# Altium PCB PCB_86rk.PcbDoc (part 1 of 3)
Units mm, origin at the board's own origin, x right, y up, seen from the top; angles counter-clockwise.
Board outline 185 x 150 mm, 2 copper layers (Top Layer, Bottom Layer); 95 components, 233 nets, 810 pads, 336 vias.
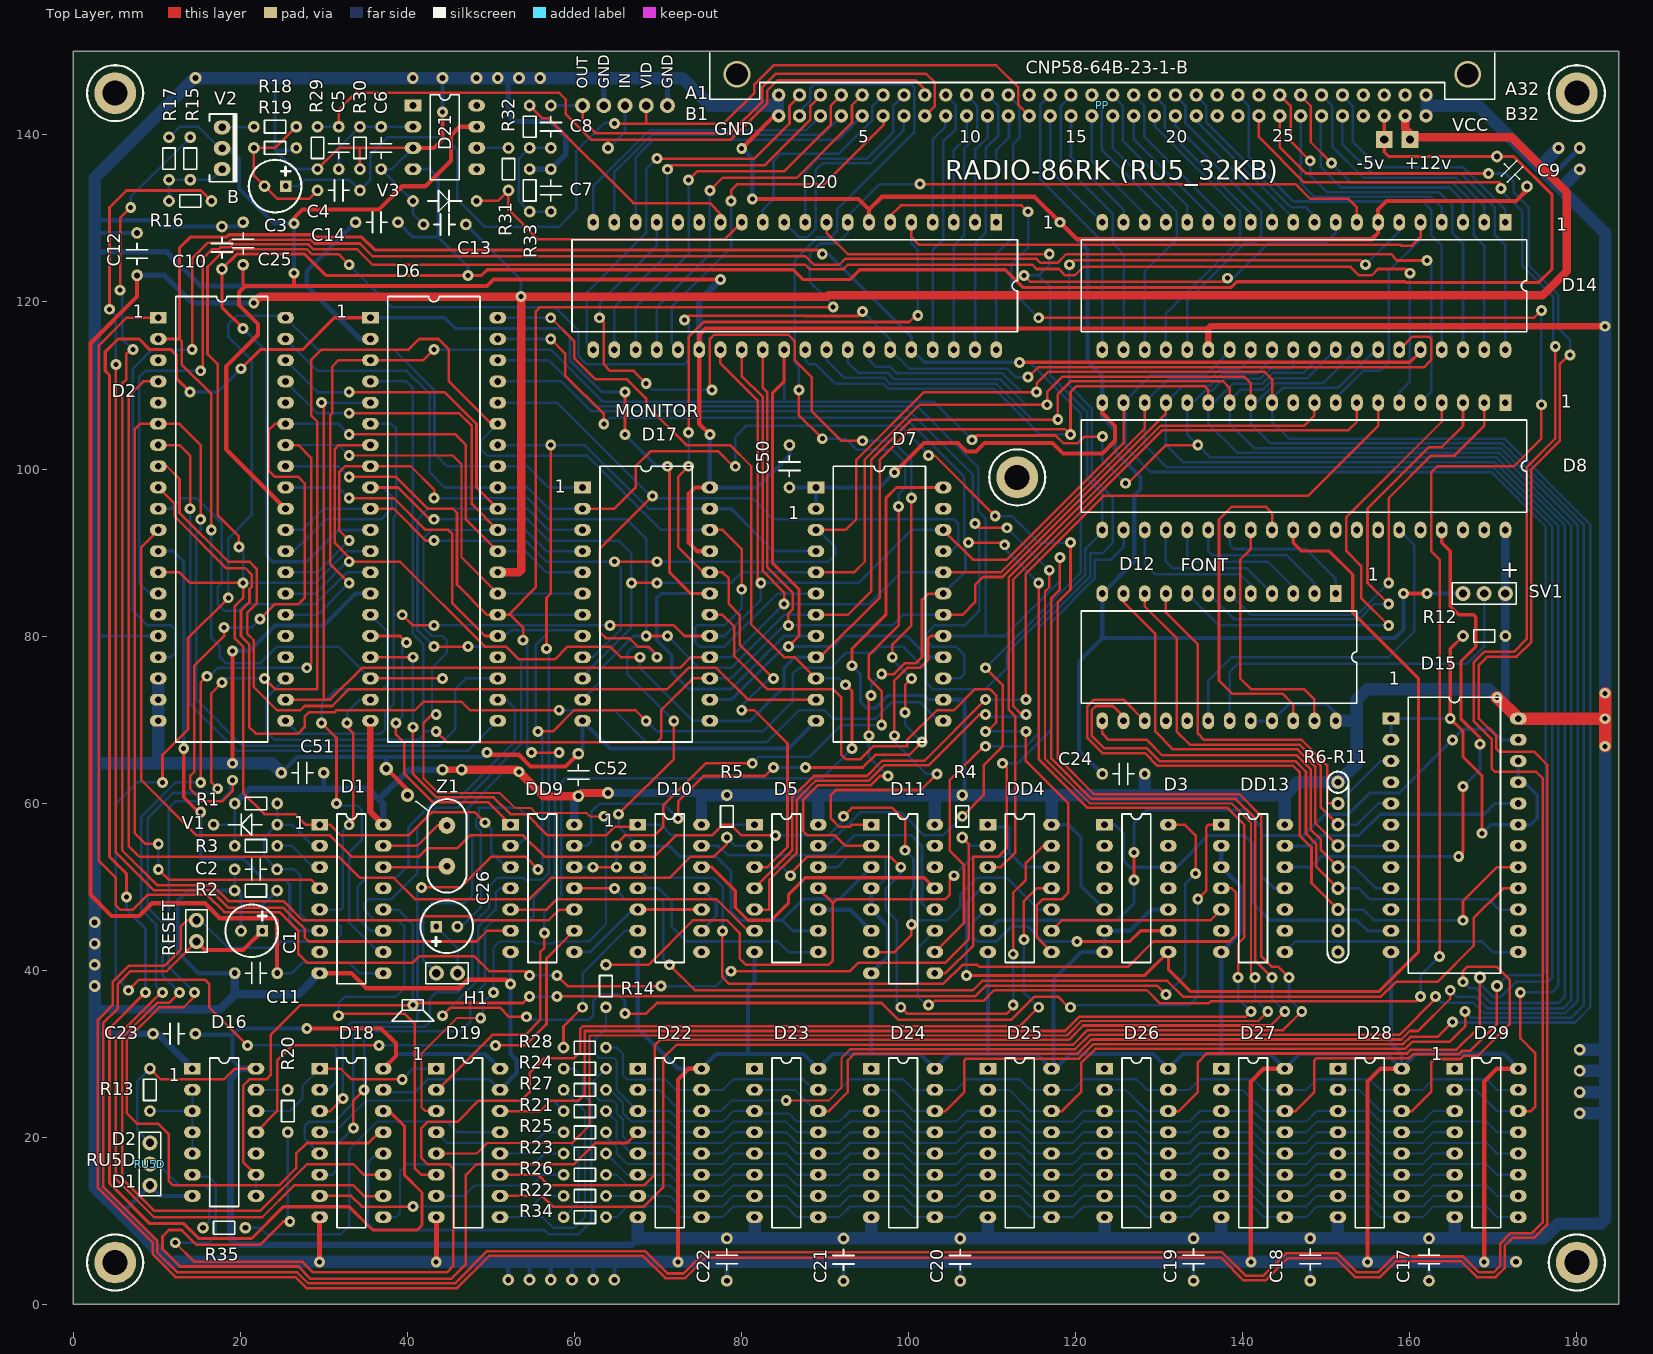
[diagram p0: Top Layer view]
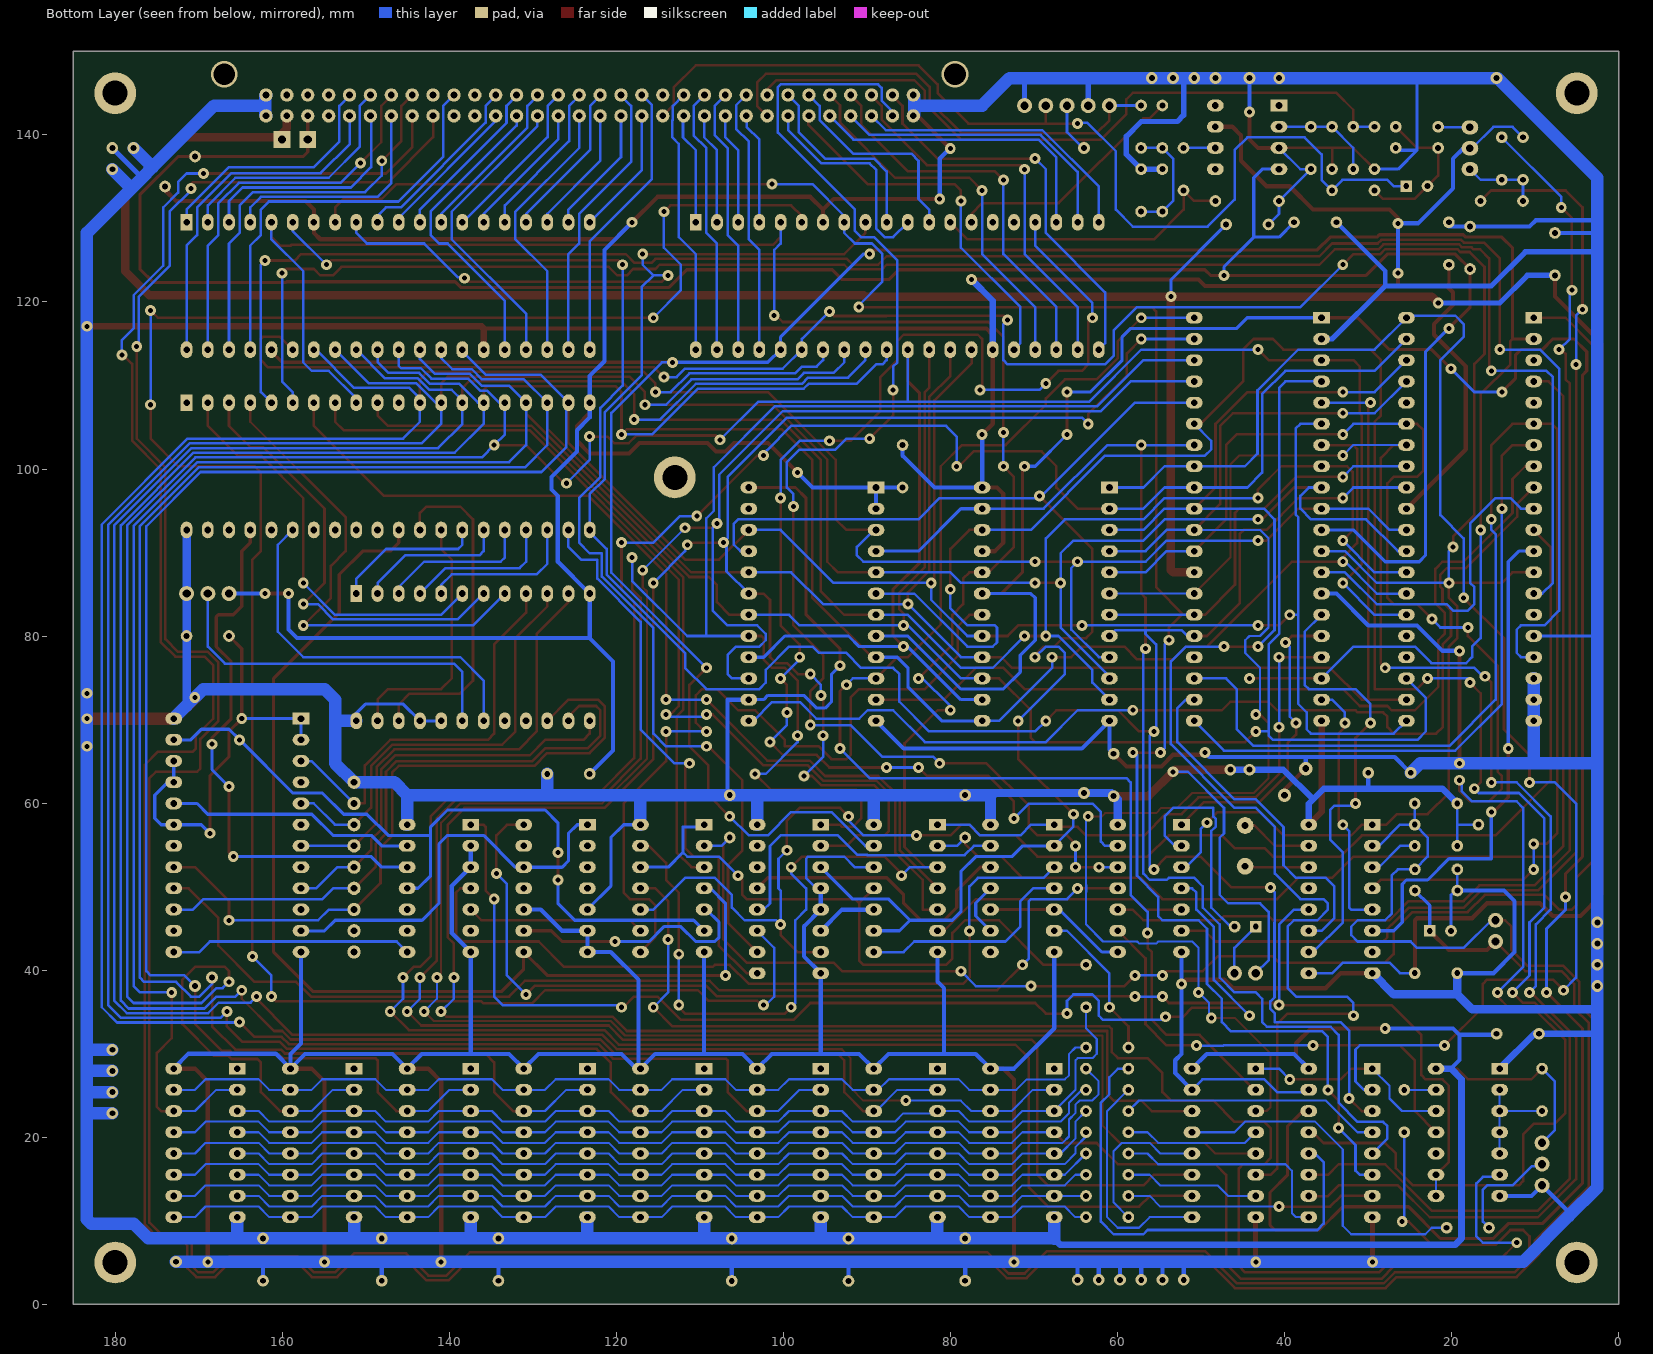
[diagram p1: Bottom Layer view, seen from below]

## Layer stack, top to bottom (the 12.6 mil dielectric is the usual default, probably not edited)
Top Layer: signal copper 0.0356
Dielectric: dielectric 0.32, FR-4, Dk 4.8
Bottom Layer: signal copper 0.0356

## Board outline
0,0 185,0 185,150 0,150

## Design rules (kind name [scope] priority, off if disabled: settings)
Clearance [All] p1: gap=0.254
ComponentClearance [All] p1: gap=0 collisioncheckmode=3 verticalgap=0 showdistances=FALSE
PolygonConnect [All] p1: connectstyle=Relief reliefconductorwidth=0.254 reliefentries=4 polygonreliefangle="90 Angle"
RoutingVias [All] p1: holewidth=0.6 width=1.3 viastyle="Through Hole" minholewidth=0.6 minwidth=1.3 maxholewidth=0.6 maxwidth=1.3
SilkscreenOverComponentPads [All] p1: minsilkscreentomaskgap=0.254
SolderMaskExpansion [All] p1: expansion=0.102
Width [All] p1: maxlimit=3 minlimit=0.254 preferedwidth=0.254
26 further rules are at their usual default settings.

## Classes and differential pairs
net class C[1..47]: C1 C2 C3 C4 C5 C6 C7 C8 C9 C10 C11 C12 C13 C14 C15 C16 C17 C18 C19 C20 C21 C22 C23 C24 C25 C26 C27 C28 C29 C30 C31 C32 C33 C34 C35 C36 C37 C38 C39 C40 C41 C42 C43 C44 C45 C46 C47
net class B[1..11]: B1 B2 B3 B4 B5 B6 B7 B8 B9 B10 B11

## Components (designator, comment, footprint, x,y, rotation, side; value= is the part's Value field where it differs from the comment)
C1 "C" Cap_2.54-6.3mm 21.336,44.704 r180 top
C2 "CAP" Cap_5mm 19.304,52.07 r0 top
C3 "C" Cap_2.54-6.3mm 24.146,133.874 r180 top
C4 "CAP" Cap_5mm 34.306,133.366 r180 top
C5 "CAP" Cap_5mm 31.766,135.906 r90 top
C6 "CAP" Cap_5mm 36.846,140.986 r270 top
C7 "CAP" Cap_5mm 57.166,130.826 r90 top
C8 "CAP" Cap_5mm 57.166,138.446 r90 top
C9 "CAP" Cap_5mm 170.434,137.414 r315 top
C10 "CAP" Cap_5mm 17.78,123.952 r90 top
C11 "CAP" Cap_5mm 24.4,39.64 r180 top
C12 "CAP" Cap_5mm 7.62,123.19 r90 top
C13 "CAP" Cap_5mm 46.99,129.286 r180 top
C14 "CAP" Cap_5mm 38.862,129.54 r180 top
C17 "CAP" Cap_5mm 162.306,7.89 r270 top
C18 "CAP" Cap_5mm 148.082,7.89 r270 top
C19 "CAP" Cap_5mm 134.112,7.89 r270 top
C20 "CAP" Cap_5mm 106.172,7.874 r270 top
C21 "CAP" Cap_5mm 92.202,7.874 r270 top
C22 "CAP" Cap_5mm 78.232,7.89 r270 top
C23 "CAP" Cap_5mm 14.605,32.385 r180 top
C24 "CAP" Cap_5mm 128.27,63.5 r180 top
C25 "CAP" Cap_5mm 20.32,124.46 r90 top
C26 "C" Cap_2.54-6.3mm 44.704,45.212 r0 top
C50 "CAP" Cap_5mm 85.725,102.87 r270 top
C51 "CAP" Cap_5mm 29.972,63.627 r180 top
C52 "CAP" Cap_5mm 60.452,65.913 r270 top
D1 "КР580ГФ24" DIP16 29.48,57.42 r0 top
D2 "КР580ИК57" DIP40_2.54 10.16,118.11 r0 top
D3 "К155ИЕ4" DIP14 123.46,57.42 r0 top
D5 "К555ЛП5" DIP14 81.55,57.42 r0 top
D6 "КР580ВМ80А" DIP40_2.54 35.56,118.11 r0 top
D7 "К589ИР12" DIP24 88.9,97.79 r0 top
D8 "КР580ВГ75" DIP40_2.54 171.45,107.95 r270 top
D10 "К555ЛА3" DIP14 67.58,57.42 r0 top
D11 "К555ИД7" DIP16 95.52,57.42 r0 top
D12 "2764" DIP24 151.13,85.09 r270 top
D14 "КР580ВВ55" DIP40_2.54 171.45,129.54 r270 top
D15 "К155ИР13" DIP24 157.75,70.12 r0 top
D16 "К155ИР1" DIP14 14.24,28.21 r0 top
D17 "2764" DIP24 60.96,97.79 r0 top
D18 "КР555КП11" DIP16 29.48,28.21 r0 top
D19 "КР555КП11" DIP16 43.45,28.21 r0 top
D20 "КР580ВВ55" DIP40_2.54 110.49,129.54 r270 top
D21 "КР140УД608" DIP8 40.656,143.526 r0 top
D22 "КР565РУ5" DIP16 67.58,28.21 r0 top
D23 "КР565РУ5" DIP16 81.55,28.21 r0 top
D24 "КР565РУ5" DIP16 95.52,28.21 r0 top
D25 "КР565РУ5" DIP16 109.49,28.21 r0 top
D26 "КР565РУ5" DIP16 123.46,28.21 r0 top
D27 "КР565РУ5" DIP16 137.43,28.21 r0 top
D28 "КР565РУ5" DIP16 151.4,28.21 r0 top
D29 "КР565РУ5" DIP16 165.37,28.21 r0 top
DD4 "К555ЛИ1" DIP14 109.49,57.42 r0 top
DD9 "К555ЛН1" DIP14 52.34,57.42 r0 top
DD13 "К555ТМ2" DIP14 137.43,57.42 r0 top
H1 "PLS-2" PLS-2 45.99,39.64 r180 top
PP "СНП58-64В-23-1-В" SNP58-64B-23-1(2) 123.19,144.78 r0 top
R1 "RES" RES_5 24.4,59.96 r180 top
R2 "RES" RES_5 19.304,49.53 r0 top
R3 "RES" RES_5 19.32,54.88 r0 top
R4 "RES" RES_5 106.426,55.88 r90 top
R5 "RES" RES_5 78.232,60.96 r270 top
R6-R11 "RES_8x" RES_8x 151.4,62.5 r270 top
R12 "RES" RES_5 171.45,80.01 r180 top
R13 "RES" RES_5 9.16,23.13 r90 top
R14 "RES" RES_5 63.754,35.56 r90 top
R15 "RES" RES_5 13.986,134.636 r90 top
R16 "RES" RES_5 16.526,132.096 r180 top
R17 "RES" RES_5 11.446,134.636 r90 top
R18 "RES" RES_5 26.686,140.986 r180 top
R19 "RES" RES_5 26.686,138.446 r180 top
R20 "RES" RES_5 25.67,20.59 r90 top
R21 "RES" RES_5 63.77,23.13 r180 top
R22 "RES" RES_5 63.77,12.97 r180 top
R23 "RES" RES_5 63.77,18.05 r180 top
R24 "RES" RES_5 63.77,28.21 r180 top
R25 "RES" RES_5 63.77,20.59 r180 top
R26 "RES" RES_5 63.77,15.51 r180 top
R27 "RES" RES_5 63.77,25.67 r180 top
R28 "RES" RES_5 63.754,30.734 r180 top
R29 "RES" RES_5 29.226,135.906 r90 top
R30 "RES" RES_5 34.306,135.906 r90 top
R31 "RES" RES_5 52.086,133.366 r90 top
R32 "RES" RES_5 54.626,138.446 r90 top
R33 "RES" RES_5 54.626,130.826 r90 top
R34 "RES" RES_5 63.77,10.43 r180 top
R35 "RES" RES_5 20.59,9.16 r180 top
RESET "PLS-2" PLS-2 14.732,43.434 r90 top (schematic designator RES)
RU5D "RU5D" PLS-3 9.16,16.78 r270 top
SV1 "PLS-3" PLS-3 168.91,85.09 r0 top
V1 "Diode" 1N4148 24.4,57.42 r180 top
V2 "KT315" KT315 17.796,135.906 r90 top
V3 "Diode" 1N4148 40.656,132.096 r0 top
Z1 "16MHz" HC49U 44.72,54.88 r0 top

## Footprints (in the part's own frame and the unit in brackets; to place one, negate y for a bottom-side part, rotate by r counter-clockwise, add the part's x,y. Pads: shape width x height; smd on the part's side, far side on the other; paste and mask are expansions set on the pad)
1N4148 [mm]
  round 1.4 hole 0.7: A(0,0) K(7.62,0)
  silkscreen extent 1.78,-1.27 5.84,1.27
Cap_2.54-6.3mm [mm]
  rect 1.4x1.4 hole 0.7: 1(-1.27,0)
  round 1.4 hole 0.7: 2(1.27,0)
  silkscreen extent -3.15,-3.15 3.15,3.15
Cap_5mm [mm]
  round 1.4 hole 0.7: 1(0,0) 2(5.08,0)
  silkscreen extent 1.27,-1.27 3.81,1.27
DIP8 [mm]
  rect 2x1.4 hole 0.8: 1(0,0)
  oval 2x1.4 hole 0.8: 2(0,-2.54) 3(0,-5.08) 4(0,-7.62) 5(7.62,-7.62) 6(7.62,-5.08) 7(7.62,-2.54) 8(7.62,0)
  silkscreen extent 2.08,-8.89 5.54,1.27
DIP14 [mm]
  rect 2x1.4 hole 0.8: 1(0,0)
  oval 2x1.4 hole 0.8: 2(0,-2.54) 3(0,-5.08) 4(0,-7.62) 5(0,-10.16) 6(0,-12.7) 7(0,-15.24) 8(7.62,-15.24) 9(7.62,-12.7) 10(7.62,-10.16) 11(7.62,-7.62) 12(7.62,-5.08) 13(7.62,-2.54) 14(7.62,0)
  silkscreen extent 2.08,-16.51 5.54,1.27
DIP16 [mm]
  rect 2x1.4 hole 0.8: 1(0,0)
  oval 2x1.4 hole 0.8: 2(0,-2.54) 3(0,-5.08) 4(0,-7.62) 5(0,-10.16) 6(0,-12.7) 7(0,-15.24) 8(0,-17.78) 9(7.62,-17.78) 10(7.62,-15.24) 11(7.62,-12.7) 12(7.62,-10.16) 13(7.62,-7.62) 14(7.62,-5.08) 15(7.62,-2.54) 16(7.62,0)
  silkscreen extent 2.08,-19.05 5.54,1.27
DIP24 [mm]
  rect 2x1.4 hole 0.8: 1(0,0)
  oval 2x1.4 hole 0.8: 2(0,-2.54) 3(0,-5.08) 4(0,-7.62) 5(0,-10.16) 6(0,-12.7) 7(0,-15.24) 8(0,-17.78) 9(0,-20.32) 10(0,-22.86) 11(0,-25.4) 12(0,-27.94) 13(15.24,-27.94) 14(15.24,-25.4) 15(15.24,-22.86) 16(15.24,-20.32) 17(15.24,-17.78) 18(15.24,-15.24) 19(15.24,-12.7) 20(15.24,-10.16) 21(15.24,-7.62) 22(15.24,-5.08) 23(15.24,-2.54) 24(15.24,0)
  silkscreen extent 2.08,-30.48 13.12,2.54
DIP40_2.54 [mm]
  rect 2x1.4 hole 0.8: 1(0,0)
  oval 2x1.4 hole 0.8: 2(0,-2.54) 3(0,-5.08) 4(0,-7.62) 5(0,-10.16) 6(0,-12.7) 7(0,-15.24) 8(0,-17.78) 9(0,-20.32) 10(0,-22.86) 11(0,-25.4) 12(0,-27.94) 13(0,-30.48) 14(0,-33.02) 15(0,-35.56) 16(0,-38.1) 17(0,-40.64) 18(0,-43.18) 19(0,-45.72) 20(0,-48.26) 21(15.24,-48.26) 22(15.24,-45.72) 23(15.24,-43.18) 24(15.24,-40.64) 25(15.24,-38.1) 26(15.24,-35.56) 27(15.24,-33.02) 28(15.24,-30.48) 29(15.24,-27.94) 30(15.24,-25.4) 31(15.24,-22.86) 32(15.24,-20.32) 33(15.24,-17.78) 34(15.24,-15.24) 35(15.24,-12.7) 36(15.24,-10.16) 37(15.24,-7.62) 38(15.24,-5.08) 39(15.24,-2.54) 40(15.24,0)
  silkscreen extent 2.08,-50.8 13.12,2.54
HC49U [mm]
  round 2 hole 0.8: 1(0,2.44) 2(0,-2.44)
  silkscreen extent -2.35,-5.6 2.35,5.6
KT315 [mm]
  oval 1.7x2 hole 0.9: B(0,0) C(2.5,0) E(5,0)
  silkscreen extent -1.5,-1.78 6.6,1.5
PLS-2 [mm]
  round 1.8 hole 1: 1(0,0) 2(2.54,0)
  silkscreen extent -1.27,-1.27 3.81,1.27
PLS-3 [mm]
  round 1.8 hole 1: 1(-2.54,0) 2(0,0) 3(2.54,0)
  silkscreen extent -3.81,-1.27 3.81,1.27
RES_5 [mm]
  round 1.4 hole 0.7: 1(0,0) 2(5.08,0)
  silkscreen extent 1.27,-0.76 3.81,0.76
RES_8x [mm]
  round 1.6 hole 0.8: 1(0,0) 2(2.54,0) 3(5.08,0) 4(7.62,0) 5(10.16,0) 6(12.7,0) 7(15.24,0) 8(17.78,0) 9(20.32,0)
  silkscreen extent -1.27,-1.27 21.59,1.27
SNP58-64B-23-1(2) [mm]
  round 1.6 hole 0.8: А1(-38.75,0) А2(-36.25,0) А3(-33.75,0) А4(-31.25,0) А5(-28.75,0) А6(-26.25,0) А7(-23.75,0) А8(-21.25,0) А9(-18.75,0) А10(-16.25,0) А11(-13.75,0) А12(-11.25,0) А13(-8.75,0) А14(-6.25,0) А15(-3.75,0) А16(-1.25,0) А17(1.25,0) А18(3.75,0) А19(6.25,0) А20(8.75,0) А21(11.25,0) А22(13.75,0) А23(16.25,0) А24(18.75,0) А25(21.25,0) А26(23.75,0) А27(26.25,0) А28(28.75,0) А29(31.25,0) А30(33.75,0) А31(36.25,0) А32(38.75,0) Б1(-38.75,-2.5) Б2(-36.25,-2.5) Б3(-33.75,-2.5) Б4(-31.25,-2.5) Б5(-28.75,-2.5) Б6(-26.25,-2.5) Б7(-23.75,-2.5) Б8(-21.25,-2.5) Б9(-18.75,-2.5) Б10(-16.25,-2.5) Б11(-13.75,-2.5) Б12(-11.25,-2.5) Б13(-8.75,-2.5) Б14(-6.25,-2.5) Б15(-3.75,-2.5) Б16(-1.25,-2.5) Б17(1.25,-2.5) Б18(3.75,-2.5) Б19(6.25,-2.5) Б20(8.75,-2.5) Б21(11.25,-2.5) Б22(13.75,-2.5) Б23(16.25,-2.5) Б24(18.75,-2.5) Б25(21.25,-2.5) Б26(23.75,-2.5) Б27(26.25,-2.5) Б28(28.75,-2.5) Б29(31.25,-2.5) Б30(33.75,-2.5) Б31(36.25,-2.5) Б32(38.75,-2.5)
  silkscreen extent -47,-0.5 47,5.08

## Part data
C1 C3 C26: library part Cap_pol
D21: library part КР140УД608_dip8
RU5D: library part PLS-3
Z1: library part HC49U

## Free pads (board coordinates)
  round 5 hole 3: 0(5,5) 0(5,145) 0(113,99) 0(180,5) 0(180,145)
  round 1.8 hole 1: 0(60.96,143.51) 1(63.5,143.51) 2(66.04,143.51) 3(68.58,143.51) 4(71.12,143.51)
  rect 2x2 hole 1: 0(156.94,139.446) 1(160.02,139.446)

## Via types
v1: diameter 1.3, hole 0.6, Top Layer to Bottom Layer, tented both sides, 301 vias
v2: diameter 1.4, hole 0.7, Top Layer to Bottom Layer, 27 vias
v3: diameter 1.4, hole 0.7, Top Layer to Bottom Layer, tented both sides, 4 vias
v4: diameter 3.2, hole 2.6, Top Layer to Bottom Layer, 2 vias
v5: diameter 1.6, hole 0.8, Top Layer to Bottom Layer, 1 vias
v6: diameter 1.6, hole 0.8, Top Layer to Bottom Layer, tented both sides, 1 vias

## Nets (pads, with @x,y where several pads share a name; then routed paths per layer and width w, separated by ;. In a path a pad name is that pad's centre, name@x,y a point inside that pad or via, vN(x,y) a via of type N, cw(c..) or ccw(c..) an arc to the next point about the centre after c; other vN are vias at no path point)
1: D2.30 D6.10 D7.3 D8.12 D14.34 D17.9 D20.34 D24.2 D24.14 | length 394.7
  Top Layer w0.305: D6.10@35.56,95.25 38.354,95.25 42.164,91.44 v1(43.18,91.44) ; v1(64.77,88.9) v1(69.85,88.9) ; D7.3@88.9,92.71 92.456,92.71 93.726,93.98 93.726,101.092 101.854,109.22 v1(115.316,109.22) 115.316,110.236 116.7,111.62 142.634,111.62 143.51,110.744 D8.12@143.51,107.95 ; D24.14@103.14,23.13 104.41,23.13 106.68,25.4 106.68,29.21 106.883,29.413 120.402,29.413 122.129,31.14 159.213,31.14 160.077,32.004 163.322,32.004 v1@165.227,33.909
  Bottom Layer w0.254: D24.2@95.52,25.67 98.06,25.67 100.6,23.13 D24.14@103.14,23.13
  Bottom Layer w0.305: D2.30@25.4,92.71 27.432,92.71 29.972,95.25 D6.10@35.56,95.25 ; v1(43.18,91.44) 54.102,91.44 56.642,88.9 v1(64.77,88.9) 65.532,88.138 65.532,80.772 62.23,77.47 D17.9@60.96,77.47 ; v1(69.85,88.9) 90.424,88.9 91.186,89.662 91.186,90.678 89.154,92.71 D7.3@88.9,92.71 ; D20.34@95.25,114.3 95.25,113.03 96.012,112.268 97.79,112.268 98.603,111.455 111.252,111.455 113.487,109.22 v1(115.316,109.22) ; D14.34@156.21,114.3 155.956,114.3 151.384,109.728 144.78,109.728 143.51,108.458 D8.12@143.51,107.95 143.51,105.664 145.542,103.632 171.323,103.632 181.61,93.345 181.61,35.56 179.781,33.731 165.659,33.731 v1@165.608,33.782
  other v1: 165.1,33.782
2: D2.29 D6.9 D7.5 D8.13 D14.33 D17.10 D20.33 D25.2 D25.14 | length 395.7
  Top Layer w0.305: D6.9@35.052,97.79 D6.9@35.56,97.79 38.862,97.79 42.672,93.98 v1(43.18,93.98) ; v1(66.802,86.36) v1(69.85,86.36) ; D7.5@88.9,87.63 93.472,87.63 94.742,88.9 94.742,101.12 101.318,107.696 v1(116.586,107.696) ; v1@116.586,107.95 116.586,109.22 118.427,111.061 140.144,111.061 140.97,110.236 D8.13@140.97,107.95 ; D25.14@117.11,23.13 118.38,23.13 120.65,25.4 120.65,28.871 122.36,30.582 159.444,30.582 160.308,31.445 164.795,31.445 166.624,33.274 v1(166.624,35.052)
  Bottom Layer w0.254: D25.2@109.49,25.67 112.03,25.67 114.57,23.13 D25.14@117.11,23.13
  Bottom Layer w0.305: D2.29@25.4,90.17 26.416,90.17 30.226,93.98 36.83,93.98 38.1,95.25 38.1,96.774 37.084,97.79 D6.9@35.56,97.79 ; v1(43.18,93.98) 54.356,93.98 56.896,91.44 65.278,91.44 66.802,89.916 v1(66.802,86.36) 66.802,81.026 60.96,75.184 D17.10@60.96,74.93 ; v1(69.85,86.36) 78.74,86.36 80.01,87.63 D7.5@88.9,87.63 ; D20.33@92.71,114.3 92.71,112.776 93.98,111.506 97.536,111.506 98.298,110.744 110.998,110.744 114.046,107.696 v1(116.586,107.696) ; D14.33@153.67,114.3 149.657,110.287 143.982,110.287 141.645,107.95 D8.13@140.97,107.95 140.97,105.41 143.307,103.073 171.092,103.073 180.848,93.317 180.848,35.814 179.324,34.29 167.386,34.29 v1(166.624,35.052)
3: D2.28 D6.8 D7.7 D8.14 D14.32 D17.11 D20.32 D22.2 D22.14 | length 458
  Top Layer w0.254: v1(85.344,24.384) 90.424,24.384 91.948,25.908 91.948,29.464 92.964,30.48
  Top Layer w0.305: v1(33.02,91.44) 31.852,92.608 31.852,99.67 32.512,100.33 D6.8@35.56,100.33 40.386,100.33 43.18,97.536 v1(43.18,96.52) ; v1(68.58,80.01) v1(71.12,80.01) ; D7.7@88.9,82.55 92.71,82.55 95.504,85.344 95.504,101.092 100.33,105.918 v1@117.602,105.918 ; 92.964,30.48 93.015,30.531 119.939,30.531 121.666,32.258 158.75,32.258 v1@163.322,36.83 ; v1(117.856,105.918) v1@117.602,105.918 ; D8.14@138.43,107.95 138.43,109.728 137.668,110.49 119.38,110.49 117.856,108.966 117.856,106.172 v1@117.602,105.918
  Bottom Layer w0.254: D22.2@67.58,25.67 70.12,25.67 72.66,23.13 D22.14@75.2,23.13 77.486,23.13 78.74,24.384 v1(85.344,24.384)
  Bottom Layer w0.305: D2.28@25.4,87.63 29.21,87.63 v1(33.02,91.44) ; v1(43.18,96.52) 54.356,96.52 56.896,93.98 66.294,93.98 68.58,91.694 v1(68.58,80.01) 67.056,80.01 62.992,75.946 62.992,74.422 D17.11@60.96,72.39 ; v1@70.993,80.137 v1(71.12,80.01) 74.93,76.2 78.74,76.2 85.09,82.55 D7.7@88.9,82.55 ; D20.32@90.17,114.3 90.17,113.03 92.253,110.947 97.028,110.947 97.79,110.185 110.49,110.185 114.757,105.918 v1(117.856,105.918) ; D14.32@151.13,114.3 147.676,110.846 143.751,110.846 142.379,109.474 139.7,109.474 138.43,108.204 D8.14@138.43,107.95 138.43,105.41 141.326,102.514 170.86,102.514 180.086,93.288 180.086,36.322 178.613,34.849 168.859,34.849 167.6,36.108 163.79,36.108 v1(163.068,36.83)
4: D2.27 D6.7 D7.9 D8.15 D14.31 D17.13 D20.31 D23.2 D23.14 | length 443.6
  Top Layer w0.305: v1(33.02,88.9) 39.116,88.9 49.276,78.74 51.816,78.74 53.34,77.216 57.658,77.216 59.182,78.74 64.262,78.74 65.532,77.47 v1(67.818,77.47) ; v1@33.02,89.408 31.293,91.135 31.293,102.413 31.75,102.87 D6.7@35.56,102.87 ; D7.9@88.9,77.47 89.408,77.47 96.52,84.582 96.52,101.092 100.203,104.775 118.745,104.775 v1(119.38,104.14) 119.38,109.22 120.091,109.931 135.433,109.931 135.89,109.474 D8.15@135.89,107.95 ; D23.14@89.17,23.13 90.44,23.13 92.71,25.4 92.71,29.21 93.472,29.972 120.17,29.972 121.897,31.699 158.981,31.699 159.997,32.715 160.985,32.715 164.846,36.576 v1(164.846,37.592) v1@164.846,38.1
  Bottom Layer w0.254: D23.2@81.55,25.67 86.344,25.67 88.884,23.13 D23.14@89.17,23.13
  Bottom Layer w0.305: D2.27@25.4,85.09 28.956,85.09 33.02,89.154 v1@33.02,89.408 ; v1(67.818,77.47) 67.818,76.2 74.168,69.85 D17.13@76.2,69.85 ; D20.31@87.63,114.3 87.63,113.03 88.138,112.522 88.9,112.522 91.186,110.236 96.949,110.236 97.559,109.626 110.236,109.626 115.722,104.14 v1(119.38,104.14) ; D14.31@148.59,114.3 148.59,112.811 147.285,111.506 143.621,111.506 142.351,110.236 138.851,110.236 136.565,107.95 D8.15@135.89,107.95 135.89,105.41 139.344,101.956 170.629,101.956 179.324,93.26 179.324,36.35 178.381,35.408 169.316,35.408 167.894,36.83 165.608,36.83 v1(164.846,37.592)
  Bottom Layer w0.381: D17.13@76.2,69.85 81.026,69.85 85.09,73.914 85.09,76.2 86.36,77.47 D7.9@88.9,77.47
5: D2.26 D6.3 D7.16 D8.16 D14.30 D17.14 D20.30 D28.2 D28.14 | length 409.9
  Top Layer w0.305: v1@32.766,86.36 32.766,86.614 30.734,88.646 30.734,106.426 30.988,106.68 30.988,112.268 31.75,113.03 D6.3@35.56,113.03 41.91,113.03 v1(43.18,114.3) ; v1(107.569,103.505) 108.077,104.013 117.602,104.013 118.531,103.084 120.229,103.084 121.031,103.886 v1(123.19,103.886) v1@123.444,104.14 ; v1(125.984,98.298) 126.238,98.298 130.81,102.87 v1(134.62,102.87) ; D28.14@159.02,23.13 160.29,23.13 162.56,25.4 162.56,28.956 162.966,29.362 166.071,29.362 166.477,29.769 168.199,29.769 171.958,33.528 171.958,38.862 170.434,40.386 166.878,40.386 166.37,39.878 v1(166.37,38.608)
  Top Layer w0.381: D20.30@85.09,114.3 85.09,110.49 83.693,109.093 83.693,88.773 86.868,85.598 86.868,80.01 v1(85.598,78.74)
  Bottom Layer w0.254: D28.2@151.4,25.67 153.94,25.67 156.48,23.13 D28.14@159.02,23.13
  Bottom Layer w0.305: D2.26@25.4,82.55 29.21,82.55 v1(33.02,86.36) v1@32.766,86.36 ; v1(43.18,114.3) 57.15,114.3 63.398,108.052 85.09,108.052 ; D20.30@85.09,114.3 85.09,108.052 ; v1(107.569,103.505) 103.022,108.052 85.09,108.052 ; v1(123.19,103.886) 123.19,101.092 v1(125.984,98.298) v1@126.111,98.171 ; D14.30@146.05,114.3 146.05,112.354 145.761,112.065 143.389,112.065 142.154,110.83 137.754,110.83 136.28,109.356 135.432,109.356 134.025,107.95 D8.16@133.35,107.95 133.35,104.14 v1(134.62,102.87) 136.093,101.397 170.397,101.397 178.562,93.232 178.562,36.83 177.8,36.068 169.672,36.068 167.894,37.846 167.132,37.846 v1(166.37,38.608)
  Bottom Layer w0.381: D17.14@76.2,72.39 78.74,72.39 85.09,78.74 v1(85.598,78.74) 90.932,78.74 92.202,80.01 99.822,80.01 102.362,77.47 D7.16@104.14,77.47
6: D2.23 D6.4 D7.18 D8.17 D14.29 D17.15 D20.29 D29.2 D29.14 | length 376.7
  Top Layer w0.305: v1(43.434,68.58) 44.704,67.31 69.85,67.31 70.358,67.818 70.358,71.12 74.168,74.93 D17.15@76.2,74.93 ; D20.29@82.55,114.3 82.55,109.728 83.096,109.182 83.096,88.227 86.146,85.177 86.146,83.225 85.598,82.677 v1(85.598,81.28) ; D7.18@104.14,82.55 106.426,82.55 107.95,84.074 107.95,86.106 108.915,87.071 111.258,87.071 130.81,106.623 D8.17@130.81,107.95 ; D29.14@172.99,23.13 174.482,23.13 174.498,23.114 175.006,23.622 175.006,30.099 173.228,31.877 v1(173.228,37.338)
  Bottom Layer w0.254: D29.2@165.37,25.67 167.91,25.67 170.45,23.13 D29.14@172.99,23.13
  Bottom Layer w0.305: D2.23@25.4,74.93 23.063,72.593 23.063,68.603 24.102,67.564 41.402,67.564 41.91,68.072 41.91,68.58 ; D6.4@35.56,110.49 39.878,110.49 40.64,109.728 40.64,80.264 41.91,78.994 41.91,68.58 ; v1(43.434,68.58) 41.91,68.58 ; D17.15@76.2,74.93 78.74,74.93 85.09,81.28 v1(85.598,81.28) 98.044,81.28 99.314,82.55 D7.18@104.14,82.55 ; D14.29@143.51,114.3 143.51,113.167 141.732,111.389 137.522,111.389 136.13,109.996 132.856,109.996 D8.17@130.81,107.95 130.81,102.87 132.842,100.838 170.166,100.838 177.8,93.204 177.8,38.1 177.038,37.338 v1(173.228,37.338)
7: D2.22 D6.5 D7.20 D8.18 D14.28 D17.16 D20.28 D26.2 D26.14 | length 390.8
  Top Layer w0.305: D2.22@25.4,72.39 29.972,72.39 ; v1(29.718,107.95) 29.972,107.696 29.972,72.39 ; D17.16@76.2,77.47 73.914,77.47 72.644,76.2 34.544,76.2 30.734,72.39 29.972,72.39 ; D20.28@80.01,114.3 80.01,111.125 82.537,108.598 82.537,87.77 85.09,85.217 v1(85.09,83.82) ; D7.20@104.14,87.63 111.026,87.63 128.27,104.874 D8.18@128.27,107.95 ; D26.14@131.08,23.13 132.35,23.13 134.62,25.4 134.62,28.956 135.687,30.023 159.676,30.023 160.133,30.48 165.608,30.48 168.402,33.274 168.402,38.608 v3@168.656,38.862
  Bottom Layer w0.254: D26.2@123.46,25.67 126,25.67 128.54,23.13 D26.14@131.08,23.13
  Bottom Layer w0.305: D2.22@24.892,72.39 D2.22@25.4,72.39 ; v1(29.718,107.95) D6.5@35.56,107.95 ; D17.16@76.2,77.47 78.74,77.47 v1(85.09,83.82) 95.25,83.82 99.06,87.63 D7.20@104.14,87.63 ; D14.28@140.97,114.3 140.97,113.284 139.633,111.947 137.291,111.947 136.087,110.744 131.064,110.744 D8.18@128.27,107.95 128.27,102.87 130.937,100.203 170.01,100.203 177.038,93.175 177.038,39.116 176.53,38.608 172.72,38.608 170.942,36.83 169.926,36.83 168.402,38.354 v3(168.402,39.116)
8: D2.21 D6.6 D7.22 D8.19 D14.27 D17.17 D20.27 D27.2 D27.14 | length 369.7
  Top Layer w0.305: v1(39.37,82.55) 40.64,81.28 v1(43.18,81.28) ; v1(64.262,81.28) 71.882,81.28 73.152,80.01 D17.17@76.2,80.01 ; D20.27@77.47,114.3 77.47,112.649 81.915,108.204 81.915,86.741 v1(82.296,86.36) ; D7.22@104.14,92.71 107.696,89.154 111.76,89.154 125.73,103.124 D8.19@125.73,107.95 ; D27.14@145.05,23.13 146.32,23.13 148.59,25.4 148.59,29.21 148.844,29.464 159.907,29.464 160.365,29.921 165.839,29.921 166.246,30.328 167.234,30.328 170.434,33.528 v3(170.434,38.1)
  Bottom Layer w0.254: D27.2@137.43,25.67 139.97,25.67 142.51,23.13 D27.14@145.05,23.13
  Bottom Layer w0.305: D2.21@25.4,69.85 26.924,68.326 36.83,68.326 37.338,68.834 37.338,70.866 38.354,71.882 38.354,82.55 ; D6.6@35.56,105.41 38.1,105.41 38.659,104.851 38.659,94.539 38.354,94.234 38.354,82.55 ; v1(39.37,82.55) 38.354,82.55 ; v1(43.18,81.28) v1(64.262,81.28) ; D17.17@76.2,80.01 77.978,80.01 82.296,84.328 v1(82.296,86.36) 93.98,86.36 100.33,92.71 D7.22@104.14,92.71 ; D14.27@138.43,114.3 138.43,114.097 135.636,111.303 129.083,111.303 D8.19@125.73,107.95 125.984,107.696 125.984,102.616 128.956,99.644 169.779,99.644 176.276,93.147 176.276,39.878 175.768,39.37 171.704,39.37 v3(170.434,38.1)
9: D2.32 D6.25 D8.21 D14.9 D17.8 D18.3 D20.9 | length 330.2
  Top Layer w0.305: D18.3@29.48,23.13 30.75,23.13 v1(32.258,24.638) ; v1(33.02,96.52) 38.354,96.52 42.164,92.71 44.856,92.71 45.364,92.202 45.364,83.922 49.276,80.01 D6.25@50.8,80.01 ; v1(41.656,49.911) 46.355,49.911 50.038,53.594 54.102,53.594 v1(55.626,52.07) ; v1(55.626,68.58) 57.404,68.58 59.944,71.12 67.31,71.12 v1(68.58,69.85) ; D20.9@90.17,129.54 90.17,128.27 92.71,125.73 v1(116.84,125.73) ; v1(113.792,123.19) 114.554,122.428 137.759,122.428 v1(138.176,122.845)
  Bottom Layer w0.305: D2.32@25.4,97.79 31.75,97.79 v1(33.02,96.52) ; v1(32.258,24.638) 32.258,32.766 33.274,33.782 41.148,33.782 41.148,34.828 41.696,35.376 41.696,36.252 41.199,36.749 41.199,45.697 41.148,45.748 41.148,49.276 v1@41.91,50.038 ; D6.25@50.8,80.01 51.613,80.01 52.324,80.721 56.642,80.721 ; v1@55.372,68.58 55.372,78.994 56.642,80.264 56.642,80.721 ; v1(55.626,68.58) 56.134,68.072 v1@56.134,52.07 ; D17.8@60.96,80.01 60.249,80.721 56.642,80.721 ; v1(68.58,69.85) 69.85,68.58 82.55,68.58 86.106,72.136 86.106,75.438 86.868,76.2 90.678,76.2 92.456,77.978 95.758,77.978 96.52,78.74 99.314,78.74 102.108,75.946 102.108,74.422 102.87,73.66 109.22,73.66 111.76,76.2 111.76,77.95 121.158,87.348 121.158,90.424 123.19,92.456 D8.21@123.19,92.71 123.19,97 121.361,98.829 121.361,106.807 116.967,111.201 116.967,121.793 115.57,123.19 ; v1(113.792,123.19) 115.57,123.19 ; v1(116.84,125.73) 116.84,124.46 115.57,123.19 ; v1(138.176,122.845) 138.267,122.936 138.938,122.936 143.002,127 149.86,127 151.13,128.27 D14.9@151.13,129.54
10: D2.33 D6.26 D14.8 D17.7 D18.6 D20.8 | length 296.8
  Top Layer w0.305: v1(33.02,99.06) 38.608,99.06 42.418,95.25 45.415,95.25 45.923,94.742 45.923,86.157 49.53,82.55 D6.26@50.8,82.55 52.07,82.55 ; v1(33.528,21.082) 33.528,24.384 v1(34.798,25.654) ; v1(53.848,79.502) 53.848,81.026 52.324,82.55 52.07,82.55 ; v1(54.864,66.04) v1(58.166,66.04) ; v1(90.972,119.38) 55.88,119.38 55.372,118.872 55.372,85.852 52.07,82.55 ; v1(101.346,134.112) 146.304,134.112 148.082,132.334 152.654,132.334 153.67,131.318 D14.8@153.67,129.54
  Bottom Layer w0.305: D2.33@25.4,100.33 31.75,100.33 v1(33.02,99.06) ; D18.6@29.48,15.51 31.004,15.51 31.496,16.002 31.496,19.05 v1(33.528,21.082) ; v1(34.798,25.654) 34.798,32.004 35.458,32.664 46.38,32.664 47.498,33.782 47.498,36.576 49.276,38.354 49.276,44.958 50.292,45.974 54.61,45.974 55.118,46.482 55.118,48.768 57.658,51.308 57.658,65.786 57.912,66.04 v1(58.166,66.04) ; D6.26@50.8,82.55 D17.7@60.96,82.55 ; v1(53.848,79.502) 54.356,78.994 54.356,66.548 v1(54.864,66.04) ; v1@91.079,119.487 88.138,122.428 88.138,125.73 89.408,127 91.44,127 92.71,128.27 D20.8@92.71,129.54 92.71,130.302 96.52,134.112 v1(101.346,134.112)
11: D2.34 D6.27 D17.6 D18.10 | length 195.6
  Top Layer w0.254: v1(33.02,101.6) 45.441,101.6 46.457,100.584 46.457,89.433 D6.27@50.8,85.09
  Top Layer w0.305: v1(10.668,37.338) 10.484,37.338 5.08,31.934 5.08,14.986 9.652,10.414 22.606,10.414 26.416,14.224 33.528,14.224 34.798,12.954 37.084,12.954 D18.10@37.1,12.97 ; v1(15.24,62.484) 15.24,74.422 v1(16.002,75.184) ; D2.34@25.4,102.87 26.924,102.87 28.448,101.346 28.448,76.708 v1(27.94,76.2)
  Bottom Layer w0.254: D2.34@25.4,102.87 31.75,102.87 v1(33.02,101.6) ; D6.27@50.8,85.09 D17.6@60.96,85.09
  Bottom Layer w0.305: v1(10.668,37.338) 9.906,38.1 9.906,45.466 8.128,47.244 8.128,58.42 12.192,62.484 v1(15.24,62.484) ; v1(16.002,75.184) 16.256,75.184 17.272,76.2 v1(27.94,76.2)
12: D2.35 D6.29 D17.5 D18.13 | length 207.8
  Top Layer w0.305: v1(14.478,37.338) 14.478,36.83 13.208,35.56 10.287,35.56 6.401,31.674 6.401,22.86 7.671,21.59 10.16,21.59 11.43,20.32 11.43,14.732 11.938,14.224 24.61,14.224 26.67,16.284 26.67,18.034 27.94,19.304 35.306,19.304 36.592,20.59 D18.13@37.1,20.59 ; v1(18.034,81.026) 18.034,80.01 14.478,76.454 14.478,63.754 13.97,63.246 13.97,61.722 15.494,60.198 17.78,60.198 19.05,61.468 v1(19.05,62.738) v1@19.05,62.992 ; v1(22.352,82.042) 24.13,83.82 26.924,83.82 27.686,84.582 27.686,98.298 26.924,99.06 24.13,99.06 23.368,99.822 23.368,104.648 24.13,105.41 D2.35@25.4,105.41 ; v1(33.02,104.14) 45.72,104.14 46.99,102.87 46.99,93.98 D6.29@50.8,90.17
  Bottom Layer w0.305: v1@14.478,37.592 v1(14.478,37.338) 11.43,40.386 11.43,59.436 12.192,60.198 17.526,60.198 18.796,61.468 18.796,62.484 v1(19.05,62.738) ; v1(18.034,81.026) 21.336,81.026 v1(22.352,82.042) ; D2.35@25.4,105.41 31.75,105.41 v1(33.02,104.14) ; D6.29@50.8,90.17 54.102,90.17 56.642,87.63 D17.5@60.96,87.63
13: D2.37 D6.30 D17.4 D19.3 | length 169.4
  Top Layer w0.254: v1(43.434,70.612) 42.926,70.612 41.91,69.596 41.91,62.992 43.688,61.214 51.054,61.214 52.832,59.436 54.737,59.436 55.372,58.801 61.468,58.801 61.849,58.42 v1(63.5,58.42) ; D19.3@43.45,23.13 42.148,23.13 41.656,23.622 41.656,29.972 45.974,34.29 v1(48.768,34.29) v1@49.022,34.29
  Top Layer w0.305: v1(33.02,106.68) 46.177,106.68 47.701,105.156 47.701,95.809 D6.30@50.8,92.71
  Bottom Layer w0.254: v1(43.434,70.612) 42.926,71.12 42.926,76.2 44.704,77.978 44.704,79.502 44.196,80.01 42.926,80.01 41.91,81.026 41.91,91.694 42.926,92.71 D6.30@50.8,92.71 ; v1@49.022,34.29 49.022,36.068 v1(50.292,37.338) 50.292,42.672 51.054,43.434 55.118,43.434 55.372,43.18 57.404,43.18 57.658,43.434 61.722,43.434 63.754,45.466 63.754,49.342 63.739,49.357 63.739,50.211 63.754,50.226 63.754,58.166 v1(63.5,58.42) v1@63.246,58.674
  Bottom Layer w0.305: D2.37@25.4,110.49 29.21,106.68 v1(33.02,106.68) ; D6.30@50.8,92.71 54.102,92.71 56.642,90.17 D17.4@60.96,90.17
14: D2.38 D6.31 D17.3 D19.6 | length 179.5
  Top Layer w0.305: v1(31.75,34.544) 32.004,34.798 39.624,34.798 40.894,33.528 40.894,16.256 41.64,15.51 D19.6@43.45,15.51 ; v1(33.02,109.22) 44.45,109.22 48.26,105.41 48.26,97.79 D6.31@50.8,95.25 ; v1(43.18,78.74) v1(47.244,78.74)
  Bottom Layer w0.305: D2.38@25.4,113.03 29.21,109.22 v1(33.02,109.22) ; v1(31.75,34.544) 31.75,36.068 32.512,36.83 38.608,36.83 39.624,37.846 39.624,45.212 38.862,45.974 36.068,45.974 34.798,47.244 34.798,48.006 35.306,48.514 38.1,48.514 41.148,51.562 41.148,57.15 43.434,59.436 45.974,59.436 53.594,67.056 53.594,76.962 51.816,78.74 v1(47.244,78.74) ; v1(43.18,78.74) 41.199,80.721 41.199,93.98 42.469,95.25 D6.31@50.8,95.25 54.356,95.25 56.896,92.71 D17.3@60.96,92.71
15: D2.39 D6.32 D17.2 D19.10 | length 317.2
  Top Layer w0.305: D19.10@51.07,12.97 56.118,12.97 57.404,11.684 68.326,11.684 70.612,13.97 70.612,29.464 72.238,31.09 119.707,31.09 121.435,32.817 144.831,32.817 v1(147.066,35.052) ; D17.2@60.96,95.25 64.77,95.25 67.31,97.79 67.31,100.33 69.088,102.108 77.216,102.108 78.994,100.33 v1(79.248,100.33) ; v1(102.362,101.6) 103.124,101.6 110.299,94.424 110.426,94.424 v1@110.553,94.297 ; v1(119.38,91.186) 119.38,85.598 117.856,84.074 117.856,65.38 122.174,61.062 139.598,61.062 142.24,58.42 142.24,41.656 143.51,40.386 144.272,40.386 v1(145.542,39.116)
  Bottom Layer w0.305: D2.39@25.4,115.57 29.21,111.76 39.878,111.76 42.672,108.966 42.672,99.568 44.45,97.79 D6.32@50.8,97.79 54.356,97.79 56.896,95.25 D17.2@60.96,95.25 ; v1(79.248,100.33) 79.248,103.886 80.518,105.156 99.06,105.156 101.981,102.235 ; v1(110.363,94.361) 112.395,94.361 115.57,91.186 v1(119.38,91.186) ; v1(145.542,39.116) 145.542,36.576 v1(147.066,35.052)
16: D2.40 D6.33 D17.1 D18.2 | length 182.8
  Top Layer w0.305: v1@6.35,37.846 6.858,37.846 7.874,38.862 15.748,38.862 16.256,38.354 16.256,35.56 v1(20.828,30.988) ; v1(10.668,62.484) 10.668,65.786 13.716,68.834 13.716,79.756 v1(18.542,84.582)
  Bottom Layer w0.305: v1(6.604,37.592) 5.08,39.116 5.08,59.944 7.62,62.484 v1(10.668,62.484) ; v1(18.542,84.582) 18.542,91.694 21.336,94.488 21.336,113.03 18.542,115.824 18.542,117.348 19.558,118.364 25.146,118.364 D2.40@25.4,118.11 29.21,114.3 38.354,114.3 43.231,109.423 43.231,101.854 44.755,100.33 D6.33@50.8,100.33 54.356,100.33 56.896,97.79 D17.1@60.96,97.79 ; v1(20.828,30.988) 30.988,30.988 31.496,30.48 31.496,26.67 30.496,25.67 D18.2@29.48,25.67
17: D6.34 D7.4 D17.23 D18.5 | length 152.6
  Top Layer w0.305: v1(56.642,78.486) 56.642,84.582 57.15,85.09 v1(57.15,102.87)
  Bottom Layer w0.305: D18.5@29.48,18.05 27.686,19.844 27.686,21.336 28.194,21.844 31.242,21.844 33.528,24.13 33.528,32.258 34.493,33.223 42.113,33.223 42.672,33.782 42.672,36.576 43.434,37.338 45.974,37.338 47.752,39.116 47.752,45.466 49.784,47.498 49.784,50.038 50.8,51.054 53.848,51.054 54.102,50.8 56.134,50.8 56.896,51.562 56.896,78.232 v1(56.642,78.486) ; D6.34@50.8,102.87 v1(57.15,102.87) 61.214,102.87 68.834,95.25 D17.23@76.2,95.25
  Bottom Layer w0.381: D17.23@76.2,95.25 78.74,95.25 83.82,90.17 D7.4@88.9,90.17
18: D6.35 D7.6 D17.22 D18.11 | length 262.1
  Top Layer w0.305: v1(12.7,37.338) 11.481,36.119 10.056,36.119 5.842,31.905 5.842,15.037 9.703,11.176 22.352,11.176 27.94,16.764 33.528,16.764 34.798,15.494 37.084,15.494 D18.11@37.1,15.51 ; v1(17.272,61.722) 16.51,62.484 16.51,73.152 v1(17.78,74.422) ; v1(22.86,74.93) 24.13,73.66 29.21,73.66 29.21,105.664 28.448,106.426 28.448,113.03 29.718,114.3 40.132,114.3 41.402,115.57 43.688,115.57 44.958,114.3 44.958,110.49 50.038,105.41 D6.35@50.8,105.41 ; D17.22@76.2,92.71 77.724,92.71 80.01,90.424 v1(80.01,85.598)
  Bottom Layer w0.305: v1(12.7,37.338) 10.668,39.37 10.668,45.72 8.89,47.498 8.89,58.166 11.938,61.214 16.764,61.214 v1(17.272,61.722) ; v1(17.78,74.422) 17.78,74.676 18.034,74.93 v1(22.86,74.93) ; D6.35@50.8,105.41 48.768,103.378 48.768,102.362 49.53,101.6 61.468,101.6 70.358,92.71 D17.22@76.2,92.71 ; v1(80.01,85.598) 80.01,83.312 77.978,81.28 74.676,81.28 74.422,81.026 74.422,79.248 74.93,78.74 77.978,78.74 84.328,85.09 D7.6@88.9,85.09
19: D6.1 D7.8 D17.19 D18.14 | length 306
  Top Layer w0.381: v1(6.35,48.768) 6.35,51.562 4.318,53.594 4.318,111.252 3.81,111.76 3.81,114.046 5.334,115.57 7.874,115.57 9.144,114.3 11.684,114.3 12.357,113.627 12.357,110.833 v1(13.97,109.22) ; v1(8.636,37.338) 4.318,33.02 4.318,14.478 9.144,9.652 13.208,9.652 14.986,7.874 21.336,7.874 25.146,11.684 33.02,11.684 35.814,8.89 41.148,8.89 41.735,9.477 41.735,13.383 39.624,15.494 39.624,21.336 37.83,23.13 D18.14@37.1,23.13 ; v1(20.066,112.014) 22.352,114.3 27.432,114.3 31.242,118.11 D6.1@35.56,118.11 ; v1(66.04,104.14) v1(66.04,109.22) ; v1(71.12,100.33) 71.374,100.076 71.374,87.63 73.914,85.09 D17.19@76.2,85.09
  Bottom Layer w0.381: v1(6.35,48.768) 6.35,47.244 8.636,44.958 v1(8.636,37.338) ; v1(13.97,109.22) 17.272,109.22 v1(20.066,112.014) ; D6.1@35.56,118.11 44.45,118.11 45.72,116.84 58.42,116.84 59.436,115.824 59.436,113.03 63.246,109.22 v1(66.04,109.22) ; v1(66.04,104.14) 69.85,100.33 v1(71.12,100.33) ; D17.19@76.2,85.09 70.358,85.09 69.85,84.582 69.85,79.502 71.628,77.724 71.628,75.692 73.66,73.66 78.74,73.66 85.09,80.01 D7.8@88.9,80.01
20: D6.40 D7.10 D19.2 | length 162.4
  Top Layer w0.305: D19.2@43.45,25.67 43.577,25.67 50.165,32.258 54.102,32.258 55.88,34.036 55.88,42.164 56.388,42.672 v1(56.388,44.45) ; v1(57.15,118.11) 59.944,115.316 59.944,113.284 62.484,110.744 66.294,110.744 68.58,108.458 68.58,107.696 73.406,102.87 78.613,102.87 81.153,100.33 81.153,81.407 85.09,77.47 86.36,77.47 D7.10@88.9,74.93 ; v1(92.456,74.168) 93.218,73.406 v1(93.218,66.548)
  Bottom Layer w0.305: D6.40@50.8,118.11 v1(57.15,118.11) ; v1(56.388,44.45) 56.388,46.99 58.42,49.022 58.42,62.484 58.928,62.992 89.662,62.992 v1(93.218,66.548) ; D7.10@88.9,74.93 91.694,74.93 v1(92.456,74.168)
21: D6.37 D7.15 D19.5 | length 295.9
  Top Layer w0.254: D19.5@43.45,18.05 48.276,18.05 49.53,19.304 59.69,19.304 61.773,21.387 61.773,32.182 118.956,32.182 120.683,33.909 141.859,33.909 v1(143.002,35.052) ; v1(116.84,87.884) 116.84,85.852 116.332,85.344 116.332,65.303 121.666,59.969 138.659,59.969 140.97,57.658 140.97,39.624 v1(141.478,39.116)
  Top Layer w0.305: v1@107.442,93.472 v1(107.95,93.472) 108.458,92.964 v1(111.76,92.964)
  Bottom Layer w0.254: v1(111.76,92.964) v1(116.84,87.884) ; v1(141.478,39.116) 141.478,36.576 v1(143.002,35.052)
  Bottom Layer w0.305: D6.37@50.8,110.49 58.42,110.49 61.976,106.934 100.076,106.934 107.696,99.314 107.696,93.726 v1(107.95,93.472) ; D7.15@104.14,74.93 106.172,74.93 106.68,75.438 106.68,77.724 105.664,78.74 102.87,78.74 102.108,79.502 102.108,80.264 103.124,81.28 106.68,81.28 108.458,83.058 108.458,92.964 v1(107.95,93.472) ; v1@107.442,93.472 v1(107.95,93.472)
22: D6.38 D7.17 D11.1 D19.11 | length 337.3
  Top Layer w0.305: D19.11@51.07,15.51 55.61,15.51 56.896,14.224 68.326,14.224 69.596,15.494 69.596,30.988 70.256,31.648 119.177,31.648 120.904,33.376 143.358,33.376 v1(145.034,35.052) ; D11.1@95.52,57.42 93.234,57.42 92.964,57.15 91.694,57.15 90.678,58.166 90.678,60.96 91.288,61.57 101.448,61.57 v1(103.378,63.5) ; v1@98.298,68.58 98.298,74.676 99.822,76.2 101.346,76.2 102.362,77.216 102.362,79.756 102.616,80.01 D7.17@104.14,80.01 ; v1(118.11,89.408) 118.11,85.598 117.094,84.582 117.094,65.329 121.92,60.503 139.141,60.503 141.503,58.141 141.503,41.123 v1(143.51,39.116)
  Bottom Layer w0.305: D6.38@50.8,113.03 56.896,113.03 62.433,107.493 101.041,107.493 108.331,100.203 108.331,94.996 109.22,94.107 109.22,80.137 109.093,80.01 ; v1@98.298,68.58 v1(98.298,68.072) 98.298,67.31 102.108,63.5 v1(103.378,63.5) ; D7.17@104.14,80.01 109.093,80.01 ; v1(118.11,89.408) 118.11,86.614 111.506,80.01 109.093,80.01 ; v1@143.51,39.37 v1(143.51,39.116) 143.51,36.576 v1(145.034,35.052)
23: D6.39 D7.19 D11.2 D19.14 | length 316.8
  Top Layer w0.305: D19.14@51.07,23.13 55.896,23.13 57.15,24.384 60.452,24.384 61.239,25.171 61.239,32.715 118.735,32.715 120.462,34.442 140.36,34.442 v1(140.97,35.052) ; v1(57.15,115.57) 58.877,113.843 58.877,111.201 63.5,106.578 v1(63.5,105.41) ; v1@95.25,68.58 95.25,72.644 v1(95.504,72.898) ; D11.2@95.52,54.88 92.44,54.88 91.186,56.134 87.884,56.134 87.376,56.642 87.376,60.395 89.109,62.128 95.459,62.128 96.577,63.246 97.068,63.246 v1@97.536,63.714 ; v1(96.774,75.438) 98.27,75.438 99.591,76.759 100.889,76.759 101.6,77.47 101.6,84.328 102.362,85.09 D7.19@104.14,85.09 ; v1(107.188,91.186) 111.252,91.186 v1(111.506,90.932) ; v1(115.57,86.36) 115.57,65.278 121.412,59.436 138.176,59.436 140.208,57.404 140.208,43.942 139.446,43.18 v1(139.446,39.116)
  Bottom Layer w0.305: D6.39@50.8,115.57 v1(57.15,115.57) ; v1(63.5,105.41) 64.248,106.158 99.582,106.158 106.68,99.06 106.68,91.694 v1(107.188,91.186) 106.807,90.805 106.807,87.757 D7.19@104.14,85.09 ; v1@95.25,68.58 v1(95.25,68.072) 95.25,65.532 v1(97.536,63.246) ; v1(95.504,72.898) 95.504,74.168 v1(96.774,75.438) v1@97.028,75.692 ; v1@111.76,90.932 111.76,90.17 v1(115.57,86.36) ; v1(139.446,39.116) 139.446,36.576 v1(140.97,35.052)
24: D5.9 D6.36 D7.21 D10.2 D11.3 | length 168.6
  Top Layer w0.305: v1(65.278,58.674) 71.882,65.278 v1(71.882,69.85) ; v1(69.342,96.774) 62.992,90.424 62.992,80.518 63.754,79.756 66.548,79.756 67.564,78.74 68.834,78.74 69.85,77.724 v1(69.85,77.47)
  Bottom Layer w0.305: D6.36@50.8,107.95 57.912,107.95 v1@69.342,96.52 ; v1(65.278,58.674) 65.278,57.182 D10.2@67.58,54.88 ; v1(69.342,96.774) v1@69.342,96.52 ; v1(69.85,77.47) 68.58,78.74 67.056,78.74 66.294,77.978 66.294,75.438 v1(71.882,69.85) ; D7.21@104.14,90.17 105.156,90.17 105.918,90.932 105.918,93.472 105.41,93.98 83.82,93.98 81.28,96.52 v1@69.342,96.52
  Bottom Layer w0.381: D10.2@67.58,54.88 71.358,54.88 72.644,53.594 76.962,53.594 78.74,51.816 78.74,46.99 79.756,45.974 84.836,45.974 ; D5.9@89.17,44.72 86.09,44.72 84.836,45.974 ; D11.3@95.52,52.34 91.694,48.514 87.376,48.514 84.836,45.974
+12V: C11.1 C12.1 C13.1 D1.9 D6.28 pad.1@160.02,139.446 PP.Б31 | length 376.1
  Top Layer w0.508: C12.1@7.62,123.19 7.62,120.65 2.032,115.062 2.032,49.022 4.572,46.482 7.874,46.482 9.398,48.006 15.748,48.006 17.526,46.228 24.13,46.228 24.384,45.974 24.384,39.656 C11.1@24.4,39.64
  Top Layer w1.016: v1(21.59,119.888) 22.352,120.65 v1(53.594,120.65) ; D6.28@50.8,87.63 53.34,87.63 53.594,87.884 v1(53.594,120.65) ; PP.Б31@159.44,142.28 159.44,140.788 160.528,139.7 172.212,139.7 178.816,133.096 178.816,123.698 175.91,120.792 90.388,120.792 90.246,120.65 v1(53.594,120.65)
  Bottom Layer w0.305: C11.1@24.4,39.64 26.178,39.64 27.432,40.894 33.02,40.894 34.29,39.624 37.084,39.624 D1.9@37.1,39.64
  Bottom Layer w0.381: C13.1@46.99,129.286 53.594,122.682 v1(53.594,120.65)
  Bottom Layer w0.635: C12.1@7.62,123.19 10.922,123.19 14.224,119.888 v1(21.59,119.888)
